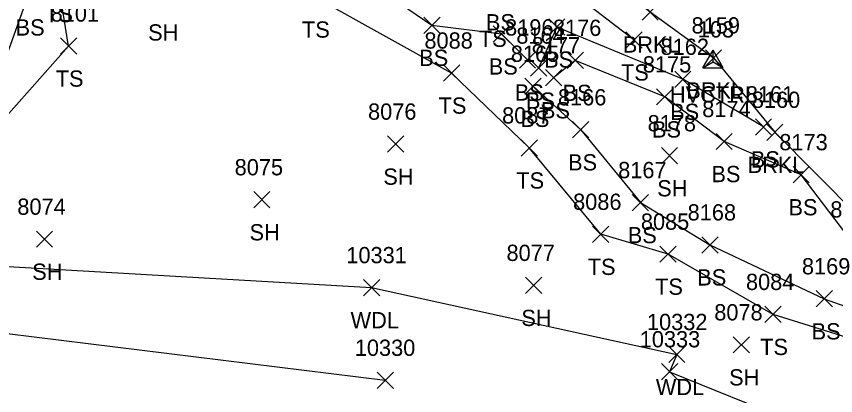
# Model space of a CAD drawing. Extents: x 1482574 to 1485769, y 580696 to 595649.
# Drawn here: x 1484969 to 1485069.7, y 581518.8 to 581565.4 of the extents above; entities that cross this region are included whole.
import ezdxf

# ---------------------------------------------------------------- set-up
doc = ezdxf.new("R2010")
doc.units = 0
for name, color, linetype in [('C_A', 7, 'Continuous'), ('C_I', 7, 'Continuous'), ('CPSM', 7, 'Continuous'), ('L_A', 7, 'Continuous'), ('L_I', 7, 'Continuous'), ('L_TIC', 7, 'Continuous'), ('LAWA', 7, 'Continuous'), ('LAWE', 7, 'Continuous'), ('LELB', 7, 'Continuous')]:
    doc.layers.add(name, color=color, linetype=linetype)

msp = doc.modelspace()

# ---------------------------------------------------------------- linework, layer by layer
at = {"layer": 'CPSM'}
for p, q in [((1485053.37, 581559.13), (1485054.62, 581561.29)), ((1485055.87, 581559.13), (1485054.62, 581561.29)), ((1485054.62, 581559.85), (1485054.62, 581561.29)), ((1485053.37, 581559.13), (1485054.62, 581559.85)), ((1485053.37, 581559.13), (1485055.87, 581559.13)), ((1485054.62, 581559.85), (1485054.62, 581559.85)), ((1485054.62, 581559.85), (1485055.87, 581559.13))]:
    msp.add_line(p, q, dxfattribs=at)
at = {"layer": 'L_TIC'}
for points in [[(1485045.89, 581564.99), (1485047.89, 581566.99)], [(1485047.89, 581564.99), (1485045.89, 581566.99)], [(1485019.06, 581563.35), (1485021.06, 581565.35)], [(1485021.06, 581563.35), (1485019.06, 581565.35)], [(1485034.42, 581563.14), (1485036.42, 581565.14)], [(1485036.42, 581563.14), (1485034.42, 581565.14)], [(1485027.61, 581562.29), (1485029.6, 581564.29)], [(1485029.6, 581562.29), (1485027.61, 581564.29)], [(1485043.9, 581561.55), (1485045.9, 581563.55)], [(1485045.9, 581561.55), (1485043.9, 581563.55)], [(1484974.4, 581560.8), (1484976.4, 581562.8)], [(1484976.4, 581560.8), (1484974.4, 581562.8)], [(1485030.81, 581559.09), (1485032.81, 581561.09)], [(1485032.81, 581559.09), (1485030.81, 581561.09)], [(1485053.68, 581559.34), (1485055.68, 581561.34)], [(1485055.68, 581559.34), (1485053.68, 581561.34)], [(1485032.18, 581558.09), (1485034.18, 581560.09)], [(1485034.18, 581558.09), (1485032.18, 581560.09)], [(1485036.69, 581559.04), (1485038.69, 581561.04)], [(1485038.69, 581559.04), (1485036.69, 581561.04)], [(1485021.48, 581557.48), (1485023.48, 581559.48)], [(1485023.48, 581557.48), (1485021.48, 581559.48)], [(1485034.02, 581556.9), (1485036.02, 581558.9)], [(1485036.02, 581556.9), (1485034.02, 581558.9)], [(1485049.91, 581556.71), (1485051.91, 581558.71)], [(1485051.91, 581556.71), (1485049.91, 581558.71)], [(1485031.5, 581555.85), (1485033.5, 581557.85)], [(1485033.5, 581555.85), (1485031.5, 581557.85)], [(1485047.68, 581554.55), (1485049.68, 581556.55)], [(1485049.68, 581554.55), (1485047.68, 581556.55)], [(1485037.36, 581550.5), (1485039.36, 581552.5)], [(1485039.36, 581550.5), (1485037.36, 581552.5)], [(1485059.83, 581550.86), (1485061.83, 581552.86)], [(1485061.83, 581550.86), (1485059.83, 581552.86)], [(1485061.22, 581550.19), (1485063.22, 581552.19)], [(1485063.22, 581550.19), (1485061.22, 581552.19)], [(1485054.99, 581549.06), (1485056.99, 581551.06)], [(1485056.99, 581549.06), (1485054.99, 581551.06)], [(1485014.6, 581548.74), (1485016.6, 581550.74)], [(1485016.6, 581548.74), (1485014.6, 581550.74)], [(1485031.03, 581548.27), (1485033.03, 581550.27)], [(1485033.03, 581548.27), (1485031.03, 581550.27)], [(1485048.27, 581547.31), (1485050.27, 581549.31)], [(1485050.27, 581547.31), (1485048.27, 581549.31)], [(1485064.46, 581544.98), (1485066.46, 581546.98)], [(1485066.46, 581544.98), (1485064.46, 581546.98)], [(1484998.15, 581541.9), (1485000.15, 581543.9)], [(1485000.15, 581541.9), (1484998.15, 581543.9)], [(1485044.7, 581541.55), (1485046.7, 581543.55)], [(1485046.7, 581541.55), (1485044.7, 581543.55)], [(1484971.43, 581537.05), (1484973.43, 581539.05)], [(1484973.43, 581537.05), (1484971.43, 581539.05)], [(1485039.81, 581537.65), (1485041.81, 581539.65)], [(1485041.81, 581537.65), (1485039.81, 581539.65)], [(1485053.24, 581536.35), (1485055.24, 581538.35)], [(1485055.24, 581536.35), (1485053.24, 581538.35)], [(1485048.09, 581535.21), (1485050.09, 581537.21)], [(1485050.09, 581535.21), (1485048.09, 581537.21)], [(1485011.64, 581531.09), (1485013.64, 581533.09)], [(1485013.64, 581531.09), (1485011.64, 581533.09)], [(1485031.57, 581531.37), (1485033.57, 581533.37)], [(1485033.57, 581531.37), (1485031.57, 581533.37)], [(1485067.3, 581529.72), (1485069.3, 581531.72)], [(1485069.3, 581529.72), (1485067.3, 581531.72)], [(1485061.01, 581527.8), (1485063.01, 581529.8)], [(1485063.01, 581527.8), (1485061.01, 581529.8)], [(1485057.11, 581524.06), (1485059.11, 581526.06)], [(1485059.11, 581524.06), (1485057.11, 581526.06)], [(1485049.17, 581522.87), (1485051.17, 581524.87)], [(1485051.17, 581522.87), (1485049.17, 581524.87)], [(1485048.28, 581520.75), (1485050.28, 581522.75)], [(1485050.28, 581520.75), (1485048.28, 581522.75)], [(1485013.33, 581519.7), (1485015.33, 581521.7)], [(1485015.33, 581519.7), (1485013.33, 581521.7)]]:
    msp.add_lwpolyline(points, dxfattribs=at)
at = {"layer": 'LAWA'}
msp.add_lwpolyline([(1484923.52, 581536.41), (1484963.67, 581534.95), (1485012.64, 581532.09), (1485050.17, 581523.87), (1485049.28, 581521.75), (1485077.54, 581510.3)], dxfattribs=at)
at = {"layer": 'LAWE'}
for points in [[(1484974.12, 581600.99), (1484984.09, 581596.62), (1484988.63, 581592.21), (1484993.23, 581582.87), (1485002.73, 581579.83), (1485005.95, 581581.57), (1485011.5, 581588.58), (1485015.2, 581588.89), (1485016.42, 581594.96), (1485023.46, 581595.32), (1485028.21, 581595.47), (1485036.86, 581583.58), (1485036.06, 581574.66), (1485046.89, 581565.99), (1485054.68, 581560.34), (1485062.22, 581551.19)], [(1485062.22, 581551.19), (1485087.69, 581525.49)]]:
    msp.add_lwpolyline(points, dxfattribs=at)
at = {"layer": 'LELB'}
for points in [[(1485097.08, 581506.94), (1485080.77, 581517.81), (1485078.03, 581523.77), (1485062.01, 581528.8), (1485049.09, 581536.21), (1485040.81, 581538.65), (1485032.03, 581549.27), (1485022.48, 581558.48), (1485005.68, 581567.83), (1484991.2, 581578.34), (1484971.63, 581594.86), (1484967.97, 581603.72)], [(1485044.9, 581562.55), (1485033.38, 581571.41), (1485025.31, 581584.04), (1485018.81, 581592.05), (1485023.97, 581595.02)], [(1484975.02, 581590.26), (1484969.91, 581584.9), (1484970.44, 581568.09), (1484966.05, 581555.94), (1484956.4, 581551.84)], [(1484955.86, 581543.83), (1484964.14, 581549.17), (1484975.4, 581561.8), (1484974.1, 581569.73), (1484974.44, 581580.02), (1484977.1, 581588.44)], [(1484998.86, 581576.86), (1485007.7, 581572.81), (1485020.06, 581564.35), (1485028.6, 581563.29), (1485031.81, 581560.09)], [(1485060.83, 581551.86), (1485050.91, 581557.71), (1485035.42, 581564.14), (1485033.18, 581559.09)], [(1485080.09, 581532.08), (1485071.73, 581537.71), (1485065.46, 581545.98), (1485055.99, 581550.06), (1485048.68, 581555.55), (1485037.69, 581560.04), (1485035.02, 581557.9)], [(1485032.5, 581556.85), (1485038.36, 581551.5), (1485045.7, 581542.55), (1485054.24, 581537.35), (1485068.3, 581530.72), (1485078.01, 581527.28)], [(1484921.82, 581525.62), (1484964.49, 581526.86), (1485014.33, 581520.7)]]:
    msp.add_lwpolyline(points, dxfattribs=at)

# ---------------------------------------------------------------- texts
at = {"layer": 'C_A'}
msp.add_text('HVCTRL', height=2, dxfattribs=at).set_placement((1485049.32, 581554.85))
at = {"layer": 'C_I'}
msp.add_text('103', height=2, dxfattribs=at).set_placement((1485052.75, 581562.85))
at = {"layer": 'L_A'}
for s, p in [('TS', (1484972.51, 581564.73)), ('BS', (1484968.88, 581563.09)), ('BS', (1485026.7, 581563.72)), ('SH', (1484985.17, 581562.47)), ('TS', (1485004.09, 581562.83)), ('TS', (1485025.84, 581561.7)), ('BRKL', (1485043.53, 581560.99)), ('BS', (1485018.5, 581559.35)), ('BS', (1485033.86, 581559.14)), ('BS', (1485027.05, 581558.29)), ('TS', (1485043.31, 581557.55)), ('TS', (1484973.81, 581556.8)), ('BS', (1485030.25, 581555.09)), ('BS', (1485036.13, 581555.04)), ('BRKL', (1485051.33, 581555.34)), ('BS', (1485031.62, 581554.09)), ('TS', (1485020.89, 581553.48)), ('BS', (1485033.46, 581552.9)), ('BS', (1485049.35, 581552.71)), ('BS', (1485030.94, 581551.85)), ('BS', (1485047.12, 581550.55)), ('BS', (1485036.8, 581546.5)), ('BRKL', (1485058.87, 581546.19)), ('BS', (1485059.27, 581546.86)), ('BS', (1485054.43, 581545.06)), ('SH', (1485014.09, 581544.74)), ('TS', (1485030.44, 581544.27)), ('SH', (1485047.76, 581543.31)), ('BS', (1485063.9, 581540.98)), ('SH', (1484997.64, 581537.9)), ('BS', (1485044.14, 581537.55)), ('SH', (1484970.92, 581533.05)), ('TS', (1485039.22, 581533.65)), ('BS', (1485052.68, 581532.35)), ('TS', (1485047.5, 581531.21)), ('WDL', (1485010.06, 581527.09)), ('SH', (1485031.06, 581527.37)), ('BS', (1485066.74, 581525.72)), ('TS', (1485060.42, 581523.8)), ('SH', (1485056.6, 581520.06)), ('WDL', (1485047.59, 581518.87))]:
    msp.add_text(s, height=2, dxfattribs=at).set_placement(p)
at = {"layer": 'L_I'}
for s, p in [('8101', (1484973.19, 581564.8)), ('8196', (1485029.06, 581563.09)), ('8159', (1485051.98, 581563.34)), ('8164', (1485030.44, 581562.09)), ('8176', (1485034.94, 581563.04)), ('8088', (1485019.14, 581561.48)), ('8177', (1485032.33, 581560.9)), ('8162', (1485048.17, 581560.71)), ('8165', (1485029.76, 581559.85)), ('8175', (1485045.99, 581558.55)), ('8166', (1485035.56, 581554.5)), ('8161', (1485058.65, 581554.86)), ('8160', (1485059.39, 581554.19)), ('8174', (1485053.29, 581553.06)), ('8076', (1485012.21, 581552.74)), ('8087', (1485028.69, 581552.27)), ('8178', (1485046.58, 581551.31)), ('8173', (1485062.77, 581548.98)), ('8075', (1484995.81, 581545.9)), ('8167', (1485042.96, 581545.55)), ('8074', (1484969.09, 581541.05)), ('8086', (1485037.42, 581541.65)), ('8168', (1485051.5, 581540.35)), ('8172', (1485069.04, 581540.71)), ('8085', (1485045.75, 581539.21)), ('10331', (1485009.54, 581535.09)), ('8077', (1485029.23, 581535.37)), ('8169', (1485065.55, 581533.72)), ('8084', (1485058.67, 581531.8)), ('8078', (1485054.77, 581528.06)), ('10332', (1485046.5, 581526.87)), ('10333', (1485045.61, 581524.75)), ('10330', (1485010.58, 581523.7))]:
    msp.add_text(s, height=2, dxfattribs=at).set_placement(p)

doc.saveas('drawing.dxf')
